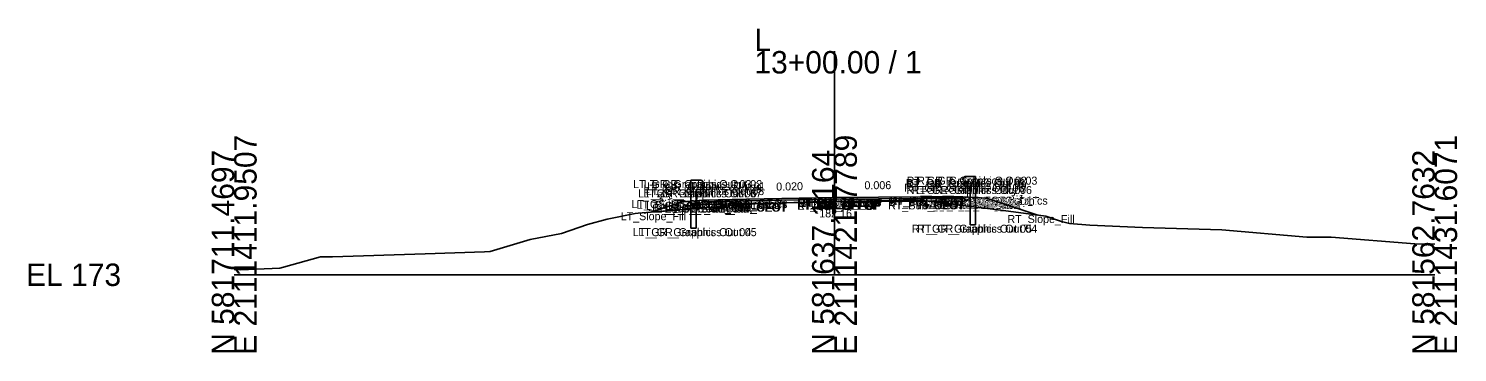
# Model space of a CAD drawing. Extents: x -26 to 3453, y -333 to 9539.
# Drawn here: x -25.7 to 152.8, y 2490.3 to 2530.7 of the extents above; entities that cross this region are included whole.
import ezdxf

# ---------------------------------------------------------------- set-up
doc = ezdxf.new("R2010")
doc.units = 0
for name, color, linetype in [('Default', 7, 'Continuous'), ('Exist Cross Section Cell', 7, 'Continuous'), ('Exist XS Center Line Elevation Label', 7, 'Continuous'), ('Exist XS Ground Line', 7, 'Continuous'), ('Prop CMT Guardrail Graphics', 7, 'Continuous'), ('Prop CMT Pvmt Course 1', 7, 'Continuous'), ('Prop CMT Pvmt Course 2', 7, 'Continuous'), ('Prop CMT Pvmt Course 3', 7, 'Continuous'), ('Prop CMT Pvmt Surface', 7, 'Continuous'), ('Prop CMT Pvmt Surface Shoulder', 7, 'Continuous'), ('Prop CMT Shld Paved Course 1', 7, 'Continuous'), ('Prop CMT Shld Paved Course 2', 7, 'Continuous'), ('Prop CMT Shld Paved Course 3', 7, 'Continuous'), ('Prop CMT Slope Grass', 7, 'Continuous'), ('Prop CMT Subgrade Earthwork', 7, 'Continuous'), ('Prop XS SE Text', 7, 'Continuous'), ('Prop XS Side Slope Text', 7, 'Continuous'), ('Scratch_Level_0', 7, 'Continuous')]:
    doc.layers.add(name, color=color, linetype=linetype)

msp = doc.modelspace()

# ---------------------------------------------------------------- linework, layer by layer
at = {"layer": 'Exist Cross Section Cell'}
for p, q in [((75, 2500), (75, 2527.93)), ((0, 2500), (75, 2500)), ((75, 2500), (150, 2500))]:
    msp.add_line(p, q, dxfattribs=at)
at = {"layer": 'Exist XS Ground Line'}
for p, q in [((50.49, 2507.68), (64.26, 2508.82)), ((64.26, 2508.82), (65.09, 2508.85)), ((65.09, 2508.85), (73.54, 2509.14)), ((73.54, 2509.14), (74.56, 2509.15)), ((74.56, 2509.15), (75, 2509.16)), ((75, 2509.16), (83.22, 2509.28)), ((83.22, 2509.28), (83.56, 2509.3)), ((83.56, 2509.3), (84.78, 2509.31)), ((84.78, 2509.31), (85.22, 2509.31)), ((85.22, 2509.31), (86.05, 2509.26)), ((86.05, 2509.26), (96.14, 2508.01)), ((44.13, 2506.26), (46.62, 2506.96)), ((46.62, 2506.96), (50.12, 2507.63)), ((50.12, 2507.63), (50.49, 2507.68)), ((96.14, 2508.01), (101.42, 2507.33)), ((101.42, 2507.33), (103.36, 2506.64)), ((103.36, 2506.64), (104.38, 2506.38)), ((36.98, 2504.4), (40.88, 2505.15)), ((40.88, 2505.15), (44.13, 2506.26)), ((104.38, 2506.38), (106.89, 2506.21)), ((106.89, 2506.21), (113.47, 2505.88)), ((113.47, 2505.88), (123.39, 2505.62)), ((123.39, 2505.62), (134.04, 2504.7)), ((32, 2502.89), (36.98, 2504.4)), ((134.04, 2504.7), (137.08, 2504.69)), ((137.08, 2504.69), (147.52, 2503.88)), ((147.52, 2503.88), (150, 2503.83)), ((6.14, 2500.94), (10.78, 2502.22)), ((10.78, 2502.22), (12.3, 2502.25)), ((12.3, 2502.25), (23.86, 2502.62)), ((23.86, 2502.62), (31.26, 2502.86)), ((31.26, 2502.86), (32, 2502.89)), ((0, 2500.64), (0.82, 2500.62)), ((0.82, 2500.62), (5.69, 2500.81)), ((5.69, 2500.81), (6.14, 2500.94))]:
    msp.add_line(p, q, dxfattribs=at)
at = {"layer": 'Prop CMT Guardrail Graphics'}
for points in [[(92.61, 2512.25), (91.28, 2512.25), (91.01, 2511.95)], [(91.01, 2511.95), (91.28, 2511.66)], [(92.61, 2506.25), (92.61, 2512.25)], [(57.04, 2505.82), (57.04, 2511.82)], [(57.04, 2511.82), (58.38, 2511.82), (58.65, 2511.53)], [(58.65, 2510.95), (58.38, 2510.66), (57.71, 2510.66)], [(57.71, 2510.66), (57.71, 2505.82)], [(58.65, 2511.53), (58.38, 2511.24)], [(58.38, 2511.24), (58.65, 2510.95)], [(91.28, 2511.66), (91.01, 2511.37)], [(91.01, 2511.37), (91.28, 2511.08), (91.95, 2511.08)], [(91.95, 2511.08), (91.95, 2506.25)], [(57.71, 2505.82), (57.04, 2505.82)], [(91.95, 2506.25), (92.61, 2506.25)]]:
    msp.add_lwpolyline(points, dxfattribs=at)
at = {"layer": 'Prop CMT Pvmt Course 1'}
for points in [[(75, 2509.65), (64, 2509.43)], [(64, 2509.22), (75, 2509.44)], [(64, 2509.43), (64, 2509.22)], [(75, 2509.65), (86, 2509.72)], [(75, 2509.44), (75, 2509.65)], [(75, 2509.44), (75, 2509.65)], [(86, 2509.51), (75, 2509.44)], [(86, 2509.72), (86, 2509.51)]]:
    msp.add_lwpolyline(points, dxfattribs=at)
msp.add_lwpolyline([(75, 2509.44), (75, 2509.53), (75, 2509.53), (75, 2509.44)], close=True, dxfattribs=at)
msp.add_lwpolyline([(75, 2509.44), (75, 2509.53), (75, 2509.53), (75, 2509.44)], close=True, dxfattribs=at)
at = {"layer": 'Prop CMT Pvmt Course 2'}
for points in [[(75, 2509.44), (64, 2509.22)], [(64, 2509.22), (64, 2508.89)], [(64, 2508.89), (75, 2509.11)], [(75, 2509.44), (86, 2509.51)], [(75, 2509.11), (75, 2509.44)], [(75, 2509.11), (75, 2509.44)], [(86, 2509.17), (75, 2509.11)], [(86, 2509.51), (86, 2509.17)]]:
    msp.add_lwpolyline(points, dxfattribs=at)
at = {"layer": 'Prop CMT Pvmt Course 3'}
for points in [[(75, 2509.11), (64, 2508.89)], [(64, 2508.89), (75, 2509.11)], [(64, 2508.89), (64, 2508.89)], [(75, 2509.11), (86, 2509.17)], [(86, 2509.17), (75, 2509.11)], [(75, 2509.11), (75, 2509.11)], [(75, 2509.11), (75, 2509.11)], [(86, 2509.17), (86, 2509.17)]]:
    msp.add_lwpolyline(points, dxfattribs=at)
at = {"layer": 'Prop CMT Pvmt Surface'}
for points in [[(75, 2509.65), (64, 2509.43)], [(75, 2509.65), (86, 2509.72)]]:
    msp.add_lwpolyline(points, dxfattribs=at)
at = {"layer": 'Prop CMT Pvmt Surface Shoulder'}
for points in [[(64, 2509.43), (58.66, 2509.32)], [(86, 2509.72), (91, 2509.75)]]:
    msp.add_lwpolyline(points, dxfattribs=at)
at = {"layer": 'Prop CMT Shld Paved Course 1'}
for points in [[(64, 2509.43), (58.66, 2509.32), (58.44, 2509.11)], [(58.44, 2509.11), (64, 2509.22)], [(64, 2509.22), (64, 2509.43)], [(86, 2509.72), (91, 2509.75), (91.21, 2509.54)], [(86, 2509.51), (86, 2509.72)], [(91.21, 2509.54), (86, 2509.51)]]:
    msp.add_lwpolyline(points, dxfattribs=at)
at = {"layer": 'Prop CMT Shld Paved Course 2'}
for points in [[(64, 2509.22), (58.44, 2509.11), (58.1, 2508.77)], [(58.1, 2508.77), (64, 2508.89)], [(64, 2508.89), (64, 2509.22)], [(86, 2509.51), (91.21, 2509.54), (91.54, 2509.21)], [(86, 2509.17), (86, 2509.51)], [(91.54, 2509.21), (86, 2509.17)]]:
    msp.add_lwpolyline(points, dxfattribs=at)
at = {"layer": 'Prop CMT Shld Paved Course 3'}
for points in [[(64, 2508.89), (58.1, 2508.77)], [(58.1, 2508.77), (64, 2508.89)], [(58.1, 2508.77), (58.1, 2508.77), (58.1, 2508.77)], [(64, 2508.89), (64, 2508.89)], [(86, 2509.17), (91.54, 2509.21)], [(91.54, 2509.21), (86, 2509.17)], [(86, 2509.17), (86, 2509.17)], [(91.54, 2509.21), (91.54, 2509.21), (91.54, 2509.21)]]:
    msp.add_lwpolyline(points, dxfattribs=at)
at = {"layer": 'Prop CMT Slope Grass'}
for points in [[(58.66, 2509.32), (56, 2509.11), (52.05, 2507.81)], [(56, 2509.11), (52.05, 2507.81)], [(58.65, 2509.32), (56, 2509.11)], [(58.66, 2509.32), (58.65, 2509.32)], [(91, 2509.75), (91.01, 2509.75)], [(91.01, 2509.75), (94, 2509.58)], [(94, 2509.58), (100.43, 2507.46)]]:
    msp.add_lwpolyline(points, dxfattribs=at)
at = {"layer": 'Prop CMT Subgrade Earthwork'}
for points in [[(58.1, 2508.77), (57.63, 2509.24)], [(64, 2508.89), (58.1, 2508.77)], [(75, 2509.11), (64, 2508.89)], [(75, 2509.11), (86, 2509.17)], [(86, 2509.17), (91.54, 2509.21)], [(91.54, 2509.21), (92.02, 2509.69)]]:
    msp.add_lwpolyline(points, dxfattribs=at)

# ---------------------------------------------------------------- texts
at = {"layer": 'Default'}
msp.add_text('-', height=0.0001, dxfattribs=at).set_placement((0, 2500))
at = {"layer": 'Exist Cross Section Cell'}
for s, p in [('L', (65, 2527.93)), ('13+00.00 / 1', (65, 2525.13)), ('EL 173', (-26, 2498.6))]:
    msp.add_text(s, height=2.8, dxfattribs=at).set_placement(p)
for s, p in [('E 2111411.9507', (2.8, 2490)), ('E 2111421.7789', (77.8, 2490)), ('E 2111431.6071', (152.8, 2490)), ('N 581711.4697', (0, 2490)), ('N 581637.1164', (75, 2490)), ('N 581562.7632', (150, 2490))]:
    msp.add_text(s, height=2.8, rotation=90, dxfattribs=at).set_placement(p)
at = {"layer": 'Exist XS Center Line Elevation Label'}
msp.add_text('182.16', height=1, dxfattribs=at).set_placement((73.1, 2507.16))
at = {"layer": 'Prop XS SE Text'}
for s, rotation, p in [('0.020', 1.1458, (67.73, 2510.5)), ('0.006', 0.3438, (78.75, 2510.67))]:
    msp.add_text(s, height=1, rotation=rotation, dxfattribs=at).set_placement(p)
at = {"layer": 'Prop XS Side Slope Text'}
for rotation, p in [(18.2629, (53.04, 2508.92)), (341.7371, (96.7, 2509.48))]:
    msp.add_text('3:1', height=1, rotation=rotation, dxfattribs=at).set_placement(p)
at = {"layer": 'Scratch_Level_0'}
for s, p in [('RT_GR_Graphics Out 01', (83.9, 2510.95)), ('RT_GR_Graphics Out 02', (84.02, 2511.25)), ('RT_GR_Graphics Out 03', (85.34, 2511.25)), ('LT_GR_Graphics Out 03', (49.83, 2510.82)), ('LT_GR_Graphics Out 06', (50.48, 2509.66)), ('LT_GR_Graphics Out 07', (51.13, 2509.66)), ('LT_GR_Graphics Out 09', (51.15, 2510.24)), ('LT_GR_Graphics Out 02', (51.18, 2510.82)), ('LT_GR_Graphics Out 08', (51.42, 2509.95)), ('LT_GR_Graphics Out 01', (51.59, 2510.53)), ('RT_GR_Graphics Out 08', (83.72, 2510.37)), ('RT_GR_Graphics Out 07', (83.98, 2510.08)), ('RT_GR_Graphics Out 09', (84, 2510.66)), ('RT_GR_Graphics Out 06', (84.66, 2510.08)), ('LT_GS_OS_GR_Face_Graphics', (49.64, 2508.32)), ('LT_Sub_Trench_Out_DLT', (50.28, 2508.24)), ('LT_GS_OS_CTL', (51.46, 2508.11)), ('LT_Sub_Trench_Out', (52.21, 2507.77)), ('LT_PS3_Shelf_Out', (52.76, 2507.77)), ('LT_PS3_OEOP', (53.89, 2507.77)), ('LT_PS2_OEOP', (54.23, 2508.11)), ('LT_PS1_OEOP', (54.56, 2508.32)), ('LT_PV2_OEOT', (59.75, 2508.22)), ('LT_PV3_OEOT', (59.75, 2507.89)), ('LT_Sub_OEOT', (59.77, 2507.89)), ('LT_PV1_OEOT', (59.87, 2508.43)), ('RT_PV2_OEEOP', (70.33, 2508.44)), ('RT_PV3_OEEOP', (70.33, 2508.11)), ('RT_Sub_OEEOP', (70.36, 2508.11)), ('LT_PV2_OEEOP', (70.39, 2508.44)), ('LT_PV3_OEEOP', (70.39, 2508.11)), ('LT_Sub_OEEOP', (70.42, 2508.11)), ('RT_PV1_OEEOP', (70.45, 2508.53)), ('LT_PV1_OEEOP', (70.51, 2508.53)), ('RT_PV2_IEEOP', (70.71, 2508.44)), ('LT_PV2_IEEOP', (70.77, 2508.44)), ('RT_PV1_IEEOP', (70.83, 2508.53)), ('LT_PV1_IEEOP', (70.89, 2508.53)), ('PV2_PGL', (72.35, 2508.44)), ('PV1_PGL', (72.47, 2508.65)), ('RT_PV2_OEOT', (81.69, 2508.51)), ('RT_PV3_OEOT', (81.69, 2508.17)), ('RT_Sub_OEOT', (81.71, 2508.17)), ('RT_PV1_OEOT', (81.81, 2508.72)), ('RT_GS_OS_GR_Face_Graphics', (81.95, 2508.75)), ('RT_Sub_Trench_Out_DLT', (84.61, 2508.69)), ('RT_Sub_Trench_Out', (85.59, 2508.21)), ('RT_PS3_Shelf_Out', (86.14, 2508.21)), ('RT_PS1_OEOP', (86.85, 2508.75)), ('RT_PS2_OEOP', (86.93, 2508.54)), ('RT_PS3_OEOP', (87.27, 2508.21)), ('RT_GS_OS_CTL', (89.4, 2508.58)), ('LT_Slope_Fill', (48.29, 2506.81)), ('RT_Slope_Fill', (96.61, 2506.46)), ('LT_GR_Graphics Out 04', (49.81, 2504.82)), ('LT_GR_Graphics Out 05', (50.49, 2504.82)), ('RT_GR_Graphics Out 05', (84.67, 2505.25)), ('RT_GR_Graphics Out 04', (85.32, 2505.25))]:
    msp.add_text(s, height=1, dxfattribs=at).set_placement(p)

doc.saveas('drawing.dxf')
